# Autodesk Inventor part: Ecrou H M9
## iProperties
Created: 2002-06
Part Number: Ecrou H M9
Material: Par défaut
Catalog Web Link: www.traceparts.com
Description: Ecrou bas hexagonal DIN 439B - M8 - 14H
Document SubType Name: Modélisation
Designer: REVEST Pierre
Control State: 0
Master: False
Checked Out: False
Shininess: 20.0
Length Units: 11269
Angle Units: 11279
Time Units: 11290
Mass Units: 11283
Length Display Precision: 3
Angle Display Precision: 2
Density: 0.0
Volumn: 0.0
Area: 0.0
PropertySet Name: Model Information
Author: REVEST Pierre
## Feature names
1. Base1
